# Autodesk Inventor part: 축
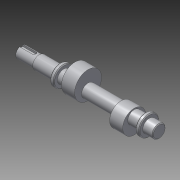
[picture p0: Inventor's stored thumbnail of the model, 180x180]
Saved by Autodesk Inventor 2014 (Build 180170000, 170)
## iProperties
Created: 2014-12
Part Number: 축
Material: 알루미늄 6061
Document SubType Name: Modeling
Designer: Owner
Mass: 170.354 g
Surface Area: 153.402 cm^2
Volume: 62.8614 cm^3
Density: 2.71 g/cm^3
Appearance: 알루미늄 - 평지
Author: Owner
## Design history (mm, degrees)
sketch "스케치1"
  geometry: L1 (-90, 0)-(90, 0); L2 (-90, 0)-(-90, 7.5); L3 (-90, 7.5)-(-66, 7.5); L4 (-66, 7.5)-(-66, 8.5); L5 (-66, 8.5)-(-39, 8.5); L6 (-39, 8.5)-(-39, 13); L7 (-39, 13)-(-34, 13); L8 (-34, 13)-(-34, 8.5); L9 (-34, 8.5)-(72, 8.5); L10 (72, 8.5)-(72, 13); L11 (72, 13)-(77, 13); L12 (77, 13)-(77, 8.5); L13 (77, 8.5)-(90, 8.5); L14 (90, 8.5)-(90, 0); 2 further points
  constraints: 28 end point, 11 parallel, 4 horizontal alignment, 2 perpendicular, 1 coincident, 1 collinear, 1 horizontal, 1 midpoint
  dimensions: "d0" = 180 distance of L1.start L1.end; "d1" = 15 diameter of L2.end L1; "d2" = 17 diameter of L5 L1; "d3" = 26 diameter of L7 L1; "d4" = 26 diameter of L11 L1; "d5" = 24 distance of L2.end L3.end; "d6" = 27 distance of L4.end L5.end; "d7" = 5 distance of L6.end L7.end; "d8" = 13 distance of L12.end L13.end
revolve "회전1" sketch "스케치1" stored, may be unused: angle "d9" = 90 deg
node "작업 평면1"
sketch "스케치2"
  geometry: C1 r 17.5 at (-6, 0); C2 r 8.5 at (0, 0) reference; 1 further point
  constraints: 1 centre point, 1 horizontal alignment
  dimensions: "d11" = 35 diameter of C1; "d12" = 6 distance of C1.centre point (0, 0)
extrude "돌출1" join sketch "스케치2" distance "d13" = 17; taper "d14" = 0 deg
node "작업 평면2"
sketch "스케치3"
  geometry: C1 r 8.5 at (0, 0) reference; C2 r 15 at (-5, 0); 1 further point
  constraints: 1 centre point, 1 horizontal alignment
  dimensions: "d16" = 30 diameter of C2; "d17" = 5 distance of C2.centre point (0, 0)
extrude "돌출2" join sketch "스케치3" distance "d18" = 17; taper "d19" = 0 deg
node "작업 평면3"
sketch "스케치4"
  geometry: L1 (-12, -7.5)-(-12, 7.5) reference; L2 (12, -7.5)-(12, 7.5) reference; L3 (-19.04, 0)-(5.5, 0); L4 (-12, -2.5)-(5.5, -2.5); L5 (5.5, 2.5)-(-12, 2.5); L6 (-12, 2.5)-(-12, -2.5); A1 r 2.5 centre (5.5, 0) between (5.5, -2.5) and (5.5, 2.5); 3 further points
  constraints: 10 end point, 3 midpoint, 2 perpendicular, 2 point on circle, 2 tangent, 1 centre point, 1 horizontal alignment, 1 parallel
  dimensions: "d20" = 5 distance of L5.end L4.start; "d21" = 20 dimension on A1 L6
extrude "돌출3" cut sketch "스케치4" distance "d22" = 3; taper "d23" = 0 deg
chamfer "모따기1" distance "d24" = 1; stored, may be unused: second distance "d25" = 2, angle "d26" = 45 deg
chamfer "모따기2" distance "d27" = 1; stored, may be unused: second distance "d28" = 2, angle "d29" = 45 deg
node "솔리드1"
node "투영된 루프1"
other parameters: "d10" = 14.5, "d15" = 14.5
